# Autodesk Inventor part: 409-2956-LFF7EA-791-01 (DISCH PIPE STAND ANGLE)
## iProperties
Shininess: 64.0
Angle Display Precision: 2
Document Length Units: 11272
Document Angle Units: 11279
Document Time Units: 11290
Document Mass Units: 11286
Document Length Units Precision: 3
Document Angle Units Precision: 2
Compacted: True
Created: 2002-04
Part Number: 409-2956-LFF7EA-791-01 (DISCH PIPE STAND ANGLE)
Description: DISCHARGE PIPE STAND ANGLE
Document SubType Name: Modeling
Designer: S. Boerckel
Mass: 4388.16 g
Surface Area: 1830.64 cm^2
Volume: 559.001 cm^3
Density: 7.85 g/cm^3
Cost Center: 2 x 2 x 1/4 ANGLE
Material: ASTM A36
Engineer: S. Boerckel
Density: 0.0
Volumn: 0.0
Area: 0.0
PropertySet Name: Model Information
Control State: 0
Master: False
Checked Out: False
length: 36.468 in
SMR: =<COST CENTER> - <MATERIAL>
Author: S. Boerckel
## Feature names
1. Extrusion1
